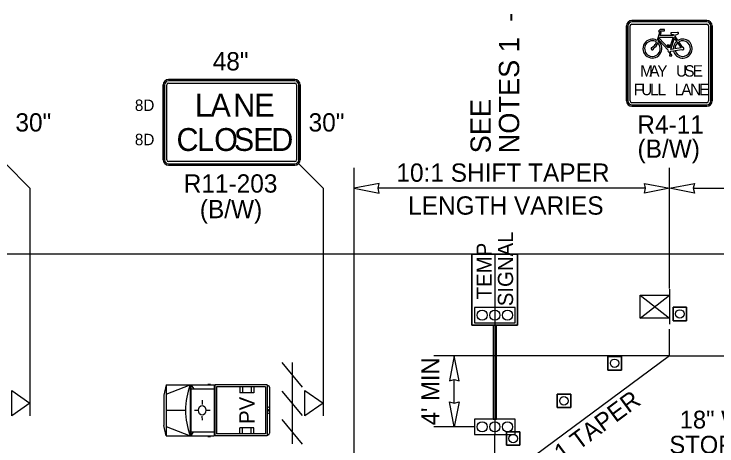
# Model space of a CAD drawing. Extents: x 99977 to 100176, y 99905 to 100011.
# Drawn here: x 100062.228 to 100064.999, y 99947.184 to 99948.886 of the extents above; entities that cross this region are included whole.
import ezdxf

# ---------------------------------------------------------------- set-up
doc = ezdxf.new("R2010")
doc.units = 0
for name, color, linetype in [('RD_ED_ShoulderPavedEdge', 7, 'Continuous'), ('RD_MK_LineEdgeWhite', 7, 'Continuous'), ('TR_SN_ConstructionSigns', 7, 'Continuous'), ('TR_WZ_BarricadeType3', 7, 'Continuous'), ('TR_WZ_PortableSignMount5ftMinBlk-Wht', 7, 'Continuous'), ('TR_WZ_PortableSignMountBlk-Wht', 7, 'Continuous'), ('TR_WZ_ProtectiveVehicle', 7, 'Continuous'), ('TR_WZ_TempSignal', 7, 'Continuous'), ('TR_WZ_TrafficCone', 7, 'Continuous'), ('TR_WZ_WorkZoneDetails', 7, 'Continuous'), ('TR_WZ_WorkZoneTextCurrent', 7, 'Continuous')]:
    doc.layers.add(name, color=color, linetype=linetype)

msp = doc.modelspace()

# ---------------------------------------------------------------- linework, layer by layer
at = {"layer": 'RD_ED_ShoulderPavedEdge'}
msp.add_line((100075.6424, 99947.9393), (100060.3, 99947.9393), dxfattribs=at)
at = {"layer": 'RD_MK_LineEdgeWhite'}
for q in [(100063.5692, 99946.6193), (100075.6425, 99947.5393)]:
    msp.add_line((100064.8112, 99947.5393), q, dxfattribs=at)
at = {"layer": 'TR_SN_ConstructionSigns'}
for p, q in [((100064.6634, 99948.8599), (100064.9588, 99948.8599)), ((100064.9588, 99948.8599), (100064.6634, 99948.8599)), ((100064.9588, 99948.8599), (100064.6634, 99948.8599)), ((100064.9588, 99948.8543), (100064.6634, 99948.8543)), ((100064.6634, 99948.8458), (100064.9588, 99948.8458)), ((100064.6423, 99948.5435), (100064.6423, 99948.8388)), ((100064.6423, 99948.8388), (100064.6423, 99948.5435)), ((100064.6423, 99948.8388), (100064.6423, 99948.5435)), ((100064.648, 99948.8388), (100064.648, 99948.5435)), ((100064.6564, 99948.5435), (100064.6564, 99948.8388)), ((100064.7751, 99948.8247), (100064.7681, 99948.8178)), ((100064.7681, 99948.8178), (100064.7728, 99948.8131)), ((100064.7916, 99948.8247), (100064.7751, 99948.8247)), ((100064.7752, 99948.8171), (100064.7774, 99948.8192)), ((100064.7792, 99948.8131), (100064.7752, 99948.8171)), ((100064.7774, 99948.8192), (100064.7916, 99948.8192)), ((100064.7916, 99948.8192), (100064.7916, 99948.8247)), ((100064.9658, 99948.8388), (100064.9658, 99948.5435)), ((100064.9742, 99948.5435), (100064.9742, 99948.8388)), ((100064.9798, 99948.8388), (100064.9798, 99948.5435)), ((100064.9798, 99948.5435), (100064.9798, 99948.8388)), ((100064.9798, 99948.5435), (100064.9798, 99948.8388)), ((100064.7728, 99948.8131), (100064.7624, 99948.782)), ((100064.7692, 99948.7831), (100064.7715, 99948.7902)), ((100064.7715, 99948.7902), (100064.7728, 99948.794)), ((100064.8062, 99948.7526), (100064.7715, 99948.7902)), ((100064.7728, 99948.794), (100064.8254, 99948.794)), ((100064.775, 99948.8006), (100064.7792, 99948.8131)), ((100064.8276, 99948.8006), (100064.775, 99948.8006)), ((100064.8254, 99948.794), (100064.811, 99948.7507)), ((100064.8164, 99948.7462), (100064.8312, 99948.7904)), ((100064.8435, 99948.8135), (100064.8186, 99948.8118)), ((100064.8288, 99948.804), (100064.8276, 99948.8006)), ((100064.8338, 99948.7983), (100064.8312, 99948.7904)), ((100064.8312, 99948.7904), (100064.8396, 99948.778)), ((100064.8338, 99948.7983), (100064.8357, 99948.8041)), ((100064.845, 99948.7818), (100064.8338, 99948.7983)), ((100064.7676, 99948.7784), (100064.7653, 99948.7717)), ((100064.7676, 99948.7784), (100064.7692, 99948.7831)), ((100064.7692, 99948.7831), (100064.8058, 99948.7433)), ((100064.8115, 99948.7633), (100064.8027, 99948.7633)), ((100064.8115, 99948.76), (100064.8115, 99948.7633)), ((100064.8396, 99948.778), (100064.8433, 99948.7725)), ((100064.8433, 99948.7725), (100064.8571, 99948.7522)), ((100064.8636, 99948.7544), (100064.8487, 99948.7763)), ((100064.8049, 99948.76), (100064.8062, 99948.7526)), ((100064.811, 99948.7507), (100064.8093, 99948.76)), ((100064.8093, 99948.76), (100064.8115, 99948.76)), ((100064.8101, 99948.7352), (100064.8137, 99948.7244)), ((100064.8183, 99948.7244), (100064.8143, 99948.7366)), ((100064.816, 99948.7395), (100064.8273, 99948.7411)), ((100064.8264, 99948.7477), (100064.8164, 99948.7462)), ((100064.8273, 99948.7411), (100064.8338, 99948.7421)), ((100064.8571, 99948.7522), (100064.8329, 99948.7486)), ((100064.8338, 99948.7421), (100064.8601, 99948.746)), ((100064.8137, 99948.7244), (100064.8119, 99948.7244)), ((100064.8119, 99948.7244), (100064.8119, 99948.7211)), ((100064.8119, 99948.7211), (100064.8207, 99948.7211)), ((100064.8207, 99948.7244), (100064.8183, 99948.7244)), ((100064.8207, 99948.7211), (100064.8207, 99948.7244)), ((100062.8369, 99948.6276), (100063.3348, 99948.6276)), ((100063.3348, 99948.6276), (100062.8369, 99948.6276)), ((100063.3348, 99948.6276), (100062.8369, 99948.6276)), ((100062.8159, 99948.3112), (100062.8159, 99948.6065)), ((100062.8159, 99948.6065), (100062.8159, 99948.3112)), ((100062.8159, 99948.6065), (100062.8159, 99948.3112)), ((100062.8215, 99948.6065), (100062.8215, 99948.3112)), ((100062.8299, 99948.3112), (100062.8299, 99948.6065)), ((100063.3348, 99948.622), (100062.8369, 99948.622)), ((100062.8369, 99948.6135), (100063.3348, 99948.6135)), ((100063.3418, 99948.6065), (100063.3418, 99948.3112)), ((100063.3502, 99948.3112), (100063.3502, 99948.6065)), ((100063.3559, 99948.6065), (100063.3559, 99948.3112)), ((100063.3559, 99948.3112), (100063.3559, 99948.6065)), ((100063.3559, 99948.3112), (100063.3559, 99948.6065)), ((100064.9588, 99948.5364), (100064.6634, 99948.5364)), ((100064.6634, 99948.528), (100064.9588, 99948.528)), ((100064.9588, 99948.5224), (100064.6634, 99948.5224)), ((100064.6634, 99948.5224), (100064.9588, 99948.5224)), ((100064.6634, 99948.5224), (100064.9588, 99948.5224)), ((100063.3348, 99948.3042), (100062.8369, 99948.3042)), ((100062.8369, 99948.2957), (100063.3348, 99948.2957)), ((100063.3348, 99948.2901), (100062.8369, 99948.2901)), ((100062.8369, 99948.2901), (100063.3348, 99948.2901)), ((100062.8369, 99948.2901), (100063.3348, 99948.2901))]:
    msp.add_line(p, q, dxfattribs=at)
msp.add_lwpolyline([(100064.8027, 99948.7633), (100064.8027, 99948.76), (100064.8049, 99948.76)], dxfattribs=at)
for centre, radius, start, end in [((100064.6634, 99948.8388), 0.0211, 90, 180), ((100064.6634, 99948.8388), 0.0211, 90, 180), ((100064.6634, 99948.8388), 0.0211, 90, 180), ((100064.6634, 99948.8388), 0.0155, 90, 180), ((100064.6634, 99948.8388), 0.00703, 90, 180), ((100064.9588, 99948.8388), 0.0211, 0, 90), ((100064.9588, 99948.8388), 0.0211, 0, 90), ((100064.9588, 99948.8388), 0.0211, 0, 90), ((100064.9588, 99948.8388), 0.0155, 0, 90), ((100064.9588, 99948.8388), 0.00703, 0, 90), ((100064.8186, 99948.8096), 0.00219, 89.3854, 243.6828), ((100064.8438, 99948.8102), 0.00329, 294.5519, 96.4128), ((100064.7441, 99948.7495), 0.0373, 60.5529, 50.868), ((100064.7441, 99948.7495), 0.0307, 58.1532, 46.1649), ((100064.8636, 99948.7495), 0.0373, 130.0889, 182.8379), ((100064.8636, 99948.7495), 0.0373, 192.9622, 119.9648), ((100064.8636, 99948.7495), 0.0307, 131.3616, 181.6359), ((100064.8636, 99948.7495), 0.0307, 193.937, 119.0598), ((100064.7441, 99948.7495), 0.00493, 105.257, 14.3233), ((100064.8106, 99948.7407), 0.00548, 151.1744, 264.8566), ((100064.8106, 99948.7407), 0.00548, 312.0053, 347.2932), ((100064.8636, 99948.7495), 0.00493, 225.1095, 90.4672), ((100062.8369, 99948.6065), 0.0211, 90, 180), ((100062.8369, 99948.6065), 0.0211, 90, 180), ((100062.8369, 99948.6065), 0.0211, 90, 180), ((100063.3348, 99948.6065), 0.0211, 0, 90), ((100063.3348, 99948.6065), 0.0211, 0, 90), ((100063.3348, 99948.6065), 0.0211, 0, 90), ((100062.8369, 99948.6065), 0.0155, 90, 180), ((100062.8369, 99948.6065), 0.00703, 90, 180), ((100063.3348, 99948.6065), 0.0155, 0, 90), ((100063.3348, 99948.6065), 0.00703, 0, 90), ((100064.6634, 99948.5435), 0.0211, 180, 270), ((100064.6634, 99948.5435), 0.0211, 180, 270), ((100064.6634, 99948.5435), 0.0211, 180, 270), ((100064.6634, 99948.5435), 0.0155, 180, 270), ((100064.6634, 99948.5435), 0.00703, 180, 270), ((100064.9588, 99948.5435), 0.0211, 270, 0), ((100064.9588, 99948.5435), 0.0211, 270, 0), ((100064.9588, 99948.5435), 0.0155, 270, 0), ((100064.9588, 99948.5435), 0.00703, 270, 0), ((100064.9588, 99948.5435), 0.0211, 270, 0), ((100062.8369, 99948.3112), 0.0211, 180, 270), ((100062.8369, 99948.3112), 0.0211, 180, 270), ((100062.8369, 99948.3112), 0.0211, 180, 270), ((100062.8369, 99948.3112), 0.0155, 180, 270), ((100062.8369, 99948.3112), 0.00703, 180, 270), ((100063.3348, 99948.3112), 0.0155, 270, 0), ((100063.3348, 99948.3112), 0.00703, 270, 0), ((100063.3348, 99948.3112), 0.0211, 270, 0), ((100063.3348, 99948.3112), 0.0211, 270, 0), ((100063.3348, 99948.3112), 0.0211, 270, 0)]:
    msp.add_arc(centre, radius, start, end, dxfattribs=at)
for centre, major_axis, ratio, start_param, end_param in [((100064.8317, 99948.8148), (-0.0186, 0), 0.588235, 0.686048, 1.410588), ((100064.8317, 99948.8148), (-0.0186, 0), 0.588235, 1.786993, 2.401245), ((100064.749, 99948.7702), (-0.0105, -0.0158), 0.413554, 0.494612, 2.170849), ((100064.749, 99948.7702), (-0.014, -0.021), 0.55814, 0.868091, 1.989998)]:
    msp.add_ellipse(centre, major_axis=major_axis, ratio=ratio, start_param=start_param, end_param=end_param, dxfattribs=at)
at = {"layer": 'TR_WZ_BarricadeType3'}
for p, q in [((100063.3648, 99947.4161), (100063.2848, 99947.5126)), ((100063.3248, 99947.5122), (100063.3248, 99947.1922)), ((100063.3648, 99947.3039), (100063.2848, 99947.4004)), ((100063.3648, 99947.1917), (100063.2848, 99947.2882))]:
    msp.add_line(p, q, dxfattribs=at)
at = {"layer": 'TR_WZ_PortableSignMount5ftMinBlk-Wht'}
for p, q in [((100064.8112, 99947.8019), (100064.8112, 99947.664)), ((100064.6962, 99947.6881), (100064.8112, 99947.7778)), ((100064.6962, 99947.7778), (100064.8112, 99947.6881)), ((100064.7535, 99947.7328), (100064.7535, 99947.7328)), ((100064.7537, 99947.7329), (100064.7537, 99947.7329))]:
    msp.add_line(p, q, dxfattribs=at)
msp.add_lwpolyline([(100064.6962, 99947.6881), (100064.6962, 99947.7778), (100064.8112, 99947.7778), (100064.8112, 99947.6881)], close=True, dxfattribs=at)
at = {"layer": 'TR_WZ_PortableSignMountBlk-Wht'}
for p, q in [((100062.291, 99947.4022), (100062.291, 99947.3022)), ((100063.4466, 99947.4022), (100063.4466, 99947.3022))]:
    msp.add_line(p, q, dxfattribs=at)
for points in [[(100062.291, 99947.3522), (100062.2192, 99947.3022), (100062.2192, 99947.4022)], [(100063.4466, 99947.3522), (100063.3748, 99947.3022), (100063.3748, 99947.4022)]]:
    msp.add_lwpolyline(points, close=True, dxfattribs=at)
at = {"layer": 'TR_WZ_ProtectiveVehicle'}
for p, q in [((100062.8282, 99947.4244), (100062.8189, 99947.3841)), ((100062.8282, 99947.4244), (100062.8282, 99947.2244)), ((100062.8282, 99947.4244), (100063.0171, 99947.4244)), ((100062.8282, 99947.3878), (100062.9226, 99947.4244)), ((100062.9226, 99947.4244), (100062.9226, 99947.2244)), ((100062.9244, 99947.4244), (100062.9244, 99947.2244)), ((100062.9244, 99947.4244), (100062.9364, 99947.4089)), ((100062.9244, 99947.4089), (100063.0171, 99947.4089)), ((100062.9913, 99947.4272), (100063.0027, 99947.4272)), ((100063.0171, 99947.4244), (100063.0171, 99947.2244)), ((100063.2256, 99947.4244), (100063.0198, 99947.4244)), ((100063.0198, 99947.4244), (100063.0198, 99947.2244)), ((100063.2197, 99947.4164), (100063.0257, 99947.4164)), ((100063.0257, 99947.4164), (100063.0257, 99947.2324)), ((100063.1184, 99947.4164), (100063.1184, 99947.3934)), ((100063.1284, 99947.4164), (100063.1284, 99947.3934)), ((100063.1624, 99947.4164), (100063.1624, 99947.3934)), ((100063.1734, 99947.4164), (100063.1734, 99947.3934)), ((100063.2197, 99947.4164), (100063.2197, 99947.2324)), ((100063.2256, 99947.4244), (100063.2256, 99947.2244)), ((100063.2307, 99947.4211), (100063.2263, 99947.4211)), ((100063.2263, 99947.4211), (100063.2263, 99947.2277)), ((100063.2352, 99947.415), (100063.2352, 99947.2338)), ((100062.8189, 99947.3841), (100062.8189, 99947.2648)), ((100063.1734, 99947.3934), (100063.1184, 99947.3934)), ((100062.9697, 99947.3641), (100062.9697, 99947.3479)), ((100062.8282, 99947.3244), (100062.9041, 99947.3244)), ((100062.9395, 99947.3246), (100062.9521, 99947.3245)), ((100062.9838, 99947.3241), (100062.9838, 99947.3241)), ((100063.0005, 99947.3237), (100062.9857, 99947.324)), ((100063.2352, 99947.3385), (100063.2263, 99947.3348)), ((100063.2328, 99947.3244), (100063.2287, 99947.3244)), ((100063.2307, 99947.3272), (100063.2307, 99947.3216)), ((100062.9704, 99947.286), (100062.9701, 99947.301)), ((100063.2352, 99947.3103), (100063.2263, 99947.3141)), ((100062.8282, 99947.2244), (100062.8189, 99947.2648)), ((100062.8282, 99947.261), (100062.9226, 99947.2244)), ((100062.9244, 99947.2399), (100063.0171, 99947.2399)), ((100062.9343, 99947.2399), (100062.9244, 99947.2244)), ((100063.1184, 99947.2324), (100063.1184, 99947.2554)), ((100063.1734, 99947.2554), (100063.1184, 99947.2554)), ((100063.1284, 99947.2324), (100063.1284, 99947.2554)), ((100063.1624, 99947.2324), (100063.1624, 99947.2554)), ((100063.1734, 99947.2324), (100063.1734, 99947.2554)), ((100062.8282, 99947.2244), (100063.0171, 99947.2244)), ((100062.9913, 99947.2216), (100063.0027, 99947.2216)), ((100063.2256, 99947.2244), (100063.0198, 99947.2244)), ((100063.2197, 99947.2324), (100063.0257, 99947.2324)), ((100063.2307, 99947.2277), (100063.2263, 99947.2277))]:
    msp.add_line(p, q, dxfattribs=at)
for centre, major_axis, start_param, end_param in [((100063.0576, 99947.3244), (0, -0.2099), 4.215667, 5.208926), ((100063.2307, 99947.415), (0, 0.0061), 4.712389, 6.283185), ((100063.2307, 99947.2338), (0, -0.0061), 0, 1.570796)]:
    msp.add_ellipse(centre, major_axis=major_axis, ratio=0.73155, start_param=start_param, end_param=end_param, dxfattribs=at)
for centre, major_axis in [((100062.9697, 99947.3244), (0, 0.0193)), ((100063.2307, 99947.3244), (0, 0.00282))]:
    msp.add_ellipse(centre, major_axis=major_axis, ratio=0.73155, dxfattribs=at)
at = {"layer": 'TR_WZ_TempSignal'}
for p, q in [((100064.033, 99947.6596), (100064.033, 99947.9397)), ((100064.033, 99947.9397), (100064.2131, 99947.9397)), ((100064.2131, 99947.9397), (100064.033, 99947.9397)), ((100064.033, 99947.9397), (100064.033, 99947.6596)), ((100064.1231, 99947.9397), (100064.1231, 99947.2294)), ((100064.2131, 99947.9397), (100064.2131, 99947.6596)), ((100064.2131, 99947.6596), (100064.2131, 99947.9397)), ((100064.203, 99947.7295), (100064.0432, 99947.7295)), ((100064.0432, 99947.7295), (100064.0432, 99947.6696)), ((100064.203, 99947.6696), (100064.203, 99947.7295)), ((100064.2131, 99947.6596), (100064.033, 99947.6596)), ((100064.033, 99947.6596), (100064.1164, 99947.6596)), ((100064.0432, 99947.6696), (100064.203, 99947.6696)), ((100064.1298, 99947.6596), (100064.1164, 99947.6596)), ((100064.1164, 99947.6596), (100064.1164, 99947.2893)), ((100064.1164, 99947.6596), (100064.1298, 99947.6596)), ((100064.1298, 99947.2893), (100064.1298, 99947.6596)), ((100064.1298, 99947.6596), (100064.2131, 99947.6596)), ((100064.203, 99947.2893), (100064.0432, 99947.2893)), ((100064.0432, 99947.2893), (100064.0432, 99947.2294)), ((100064.1164, 99947.2893), (100064.1298, 99947.2893)), ((100064.203, 99947.2294), (100064.203, 99947.2893)), ((100064.0432, 99947.2294), (100064.203, 99947.2294))]:
    msp.add_line(p, q, dxfattribs=at)
for points in [[(100064.0432, 99947.7295), (100064.0432, 99947.6696), (100064.203, 99947.6696), (100064.203, 99947.7295), (100064.0432, 99947.7295)], [(100064.0432, 99947.2893), (100064.0432, 99947.2294), (100064.203, 99947.2294), (100064.203, 99947.2893), (100064.0432, 99947.2893)]]:
    msp.add_lwpolyline(points, dxfattribs=at)
for centre in [(100064.0731, 99947.6995), (100064.0731, 99947.6995), (100064.1231, 99947.6995), (100064.1231, 99947.6995), (100064.173, 99947.6995), (100064.173, 99947.6995), (100064.0731, 99947.2593), (100064.0731, 99947.2593), (100064.1231, 99947.2593), (100064.1231, 99947.2593), (100064.173, 99947.2593), (100064.173, 99947.2593)]:
    msp.add_circle(centre, 0.02, dxfattribs=at)
at = {"layer": 'TR_WZ_TrafficCone'}
for points in [[(100064.8789, 99947.6773), (100064.8256, 99947.6773), (100064.8256, 99947.7306), (100064.8789, 99947.7306), (100064.8789, 99947.6773)], [(100064.8789, 99947.7306), (100064.8256, 99947.7306), (100064.8256, 99947.6773), (100064.8789, 99947.6773), (100064.8789, 99947.7306)], [(100064.6221, 99947.4832), (100064.5687, 99947.4832), (100064.5687, 99947.5366), (100064.6221, 99947.5366), (100064.6221, 99947.4832)], [(100064.6221, 99947.5366), (100064.5687, 99947.5366), (100064.5687, 99947.4832), (100064.6221, 99947.4832), (100064.6221, 99947.5366)], [(100064.4221, 99947.3351), (100064.3687, 99947.3351), (100064.3687, 99947.3884), (100064.4221, 99947.3884), (100064.4221, 99947.3351)], [(100064.4221, 99947.3884), (100064.3687, 99947.3884), (100064.3687, 99947.3351), (100064.4221, 99947.3351), (100064.4221, 99947.3884)], [(100064.2221, 99947.1869), (100064.1687, 99947.1869), (100064.1687, 99947.2403), (100064.2221, 99947.2403), (100064.2221, 99947.1869)], [(100064.2221, 99947.2403), (100064.1687, 99947.2403), (100064.1687, 99947.1869), (100064.2221, 99947.1869), (100064.2221, 99947.2403)]]:
    msp.add_lwpolyline(points, dxfattribs=at)
for centre in [(100064.8523, 99947.704), (100064.5954, 99947.5099), (100064.3954, 99947.3617), (100064.1954, 99947.2136)]:
    msp.add_circle(centre, 0.0167, dxfattribs=at)
at = {"layer": 'TR_WZ_WorkZoneDetails'}
for p, q in [((100062.1941, 99948.2963), (100062.291, 99948.1993)), ((100063.3497, 99948.2963), (100063.4466, 99948.1993)), ((100063.5692, 99946.2193), (100063.5692, 99948.2793)), ((100064.8112, 99947.804), (100064.8112, 99948.2793)), ((100062.291, 99948.1993), (100062.291, 99947.4022)), ((100063.4466, 99948.1993), (100063.4466, 99947.4022)), ((100064.7175, 99948.1993), (100063.6629, 99948.1993)), ((100064.9049, 99948.1993), (100065.4071, 99948.1993)), ((100064.8112, 99947.5393), (100064.8112, 99947.644)), ((100064.0432, 99947.5393), (100063.8832, 99947.5393)), ((100064.8112, 99947.5393), (100064.0432, 99947.5393)), ((100063.9632, 99947.353), (100063.9632, 99947.4456)), ((100064.0432, 99947.2593), (100063.8832, 99947.2593)), ((100064.1231, 99944.9817), (100064.1231, 99947.2294))]:
    msp.add_line(p, q, dxfattribs=at)
for points in [[(100063.5692, 99948.1993), (100063.6675, 99948.18), (100063.6629, 99948.1993), (100063.6675, 99948.2186)], [(100064.8112, 99948.1993), (100064.7129, 99948.18), (100064.7175, 99948.1993), (100064.7129, 99948.2186)], [(100064.8112, 99948.1993), (100064.9095, 99948.2186), (100064.9049, 99948.1993), (100064.9095, 99948.18)], [(100063.9632, 99947.5393), (100063.9439, 99947.441), (100063.9632, 99947.4456), (100063.9825, 99947.441)], [(100063.9632, 99947.2593), (100063.9439, 99947.3576), (100063.9632, 99947.353), (100063.9825, 99947.3576)]]:
    msp.add_lwpolyline(points, close=True, dxfattribs=at)

# ---------------------------------------------------------------- texts
at = {"layer": 'TR_SN_ConstructionSigns'}
for s, p in [('48"', (100063.0111, 99948.6636)), ('30"', (100062.2335, 99948.4228)), ('30"', (100063.3891, 99948.4228)), ('R4-11', (100064.6848, 99948.4144)), ('(B/W)', (100064.6856, 99948.3193)), ('R11-203', (100062.8969, 99948.1821)), ('(B/W)', (100062.9603, 99948.0813))]:
    msp.add_text(s, height=0.072, rotation=360, dxfattribs=at).set_placement(p)
for s, height, p in [('M', 0.045, (100064.6961, 99948.6391)), ('A', 0.045, (100064.7321, 99948.6391)), ('Y', 0.045, (100064.7636, 99948.6391)), ('U', 0.045, (100064.8374, 99948.6391)), ('S', 0.045, (100064.8703, 99948.6391)), ('E', 0.045, (100064.9031, 99948.6391)), ('F', 0.045, (100064.6709, 99948.566)), ('U', 0.045, (100064.7002, 99948.566)), ('L', 0.045, (100064.7353, 99948.566)), ('L', 0.045, (100064.7645, 99948.566)), ('L', 0.045, (100064.8325, 99948.566)), ('A', 0.045, (100064.8581, 99948.566)), ('N', 0.045, (100064.8932, 99948.566)), ('E', 0.045, (100064.9283, 99948.566)), ('L', 0.09, (100062.941, 99948.4813)), ('A', 0.09, (100063.0022, 99948.4813)), ('N', 0.09, (100063.0922, 99948.4813)), ('E', 0.09, (100063.175, 99948.4813)), ('8D', 0.045, (100062.7043, 99948.5038)), ('C', 0.09, (100062.8685, 99948.3463)), ('L', 0.09, (100062.9495, 99948.3463)), ('O', 0.09, (100063.017, 99948.3463)), ('S', 0.09, (100063.0944, 99948.3463)), ('E', 0.09, (100063.1709, 99948.3463)), ('D', 0.09, (100063.242, 99948.3463)), ('8D', 0.045, (100062.7043, 99948.3688))]:
    msp.add_text(s, height=height, dxfattribs=at).set_placement(p)
at = {"layer": 'TR_WZ_ProtectiveVehicle'}
msp.add_text('PV', height=0.06, rotation=90, dxfattribs=at).set_placement((100063.1759, 99947.2707))
at = {"layer": 'TR_WZ_TempSignal'}
for s, p in [('SIGNAL', (100064.1951, 99947.7346)), ('TEMP', (100064.1111, 99947.7617))]:
    msp.add_text(s, height=0.06, rotation=90, dxfattribs=at).set_placement(p)
at = {"layer": 'TR_WZ_WorkZoneTextCurrent'}
for s, height, rotation, p in [('-', 0.08, 90, (100064.2191, 99948.8547)), ('NOTES 1', 0.08, 90, (100064.2191, 99948.3369)), ('SEE', 0.08, 90, (100064.1071, 99948.3369)), ("4' MIN", 0.07, 90, (100063.9039, 99947.2654)), ('10:1 TAPER', 0.07, 36.5289, (100064.2858, 99947.0415))]:
    msp.add_text(s, height=height, rotation=rotation, dxfattribs=at).set_placement(p)
for s, height, p in [('10:1 SHIFT TAPER', 0.072, (100063.7352, 99948.2249)), ('LENGTH VARIES', 0.072, (100063.7813, 99948.0953)), ('18" WHITE', 0.07, (100064.8518, 99947.2529)), ('STOP BAR', 0.07, (100064.8112, 99947.1541))]:
    msp.add_text(s, height=height, dxfattribs=at).set_placement(p)

doc.saveas('drawing.dxf')
